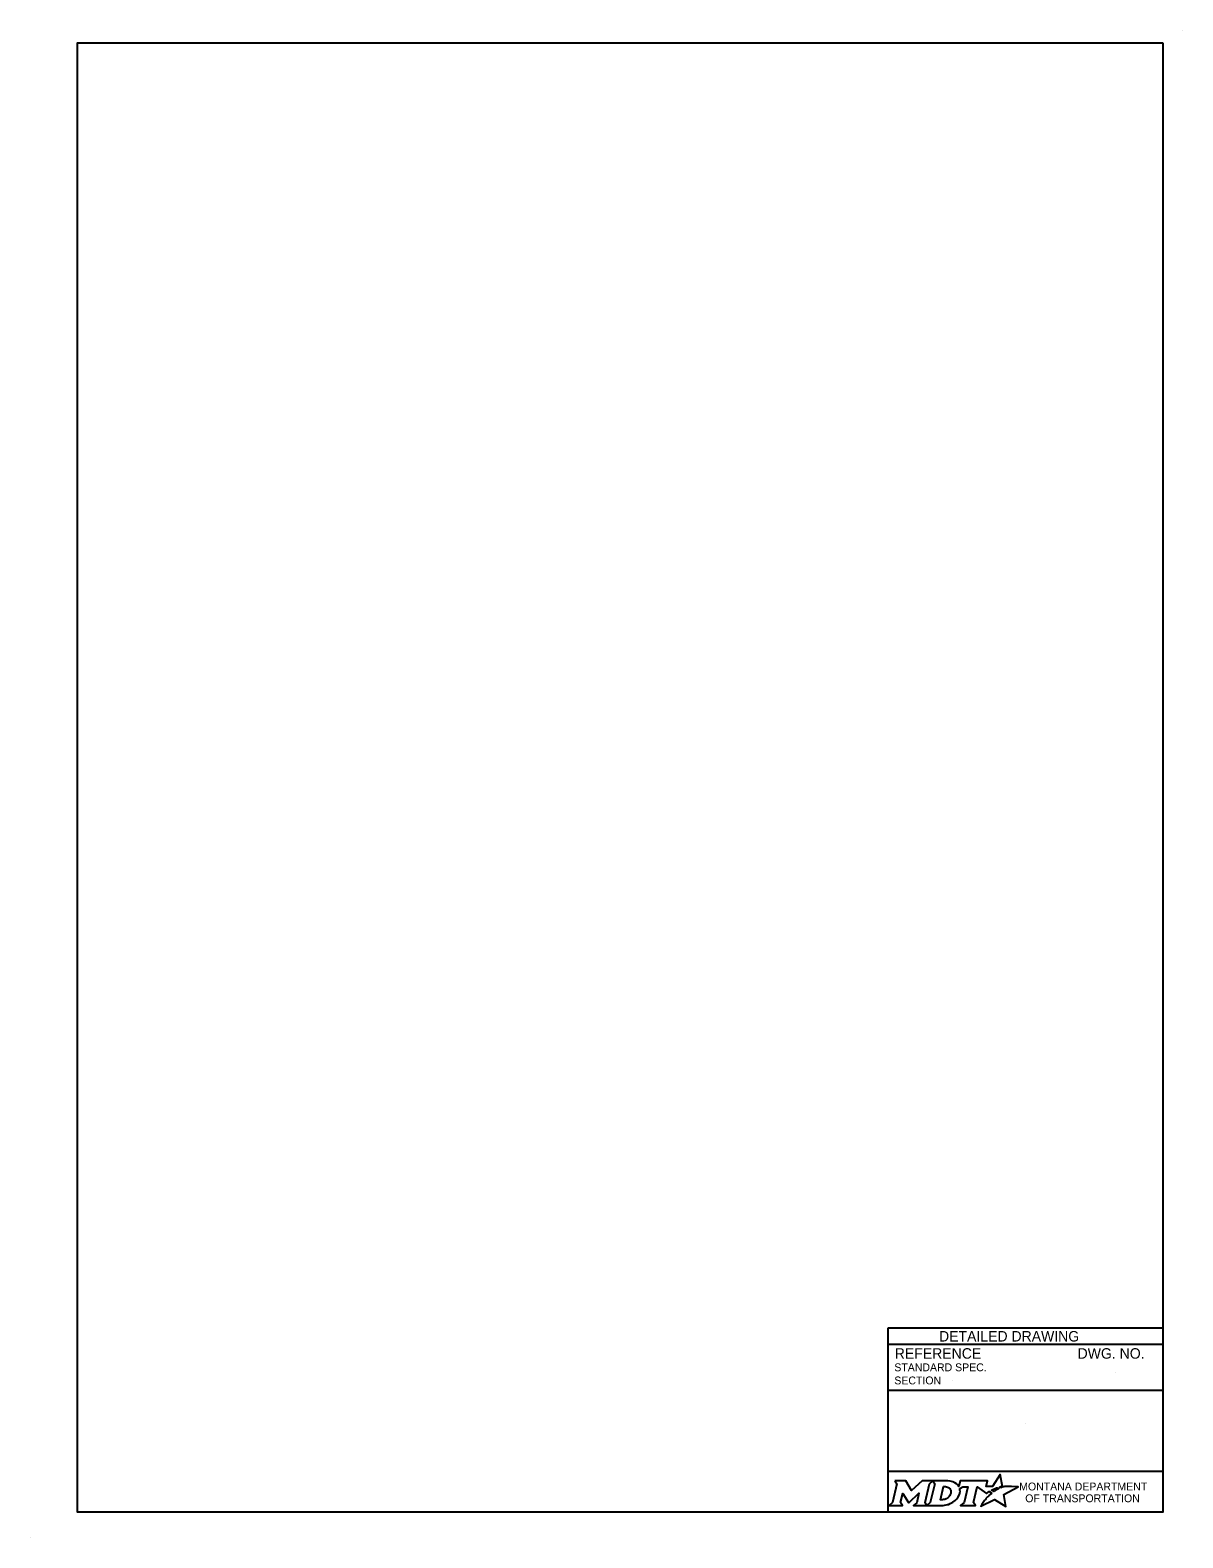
# Model space of a CAD drawing. Extents: x 49991 to 79985, y 47703 to 60542.
# Drawn here: x 49999.98 to 50008.76, y 49999.86 to 50011.36 of the extents above; entities that cross this region are included whole.
import ezdxf

# ---------------------------------------------------------------- set-up
doc = ezdxf.new("R2010")
doc.units = 0
doc.layers.add('Level 1', color=7, linetype='Continuous')
doc.layers.add('Level 2', color=7, linetype='Continuous')

msp = doc.modelspace()

# ---------------------------------------------------------------- linework, layer by layer
at = {"layer": 'Level 1'}
for p, q in [((50008.765, 50011.363), (50008.765, 50011.363)), ((49999.977, 49999.862), (49999.977, 49999.862))]:
    msp.add_line(p, q, dxfattribs=at)
msp.add_lwpolyline([(50008.615, 50011.263), (50000.336, 50011.263), (50000.336, 50000.062), (50008.615, 50000.062)], close=True, dxfattribs=at)
at = {"layer": 'Level 2'}
for p, q in [((50008.615, 50001.462), (50006.515, 50001.462)), ((50006.515, 50001.462), (50006.515, 50000.062)), ((50008.615, 50001.337), (50006.515, 50001.337)), ((50008.251, 50001.122), (50008.251, 50001.122)), ((50008.615, 50000.987), (50006.515, 50000.987)), ((50007.009, 50001.063), (50007.009, 50001.063)), ((50007.565, 50000.738), (50007.565, 50000.738)), ((50008.615, 50000.369), (50006.515, 50000.369))]:
    msp.add_line(p, q, dxfattribs=at)
for points in [[(50006.57, 50000.297), (50006.584, 50000.274), (50006.551, 50000.131), (50006.525, 50000.108), (50006.627, 50000.108), (50006.613, 50000.131), (50006.629, 50000.201), (50006.673, 50000.132), (50006.678, 50000.132), (50006.753, 50000.202), (50006.737, 50000.13), (50006.712, 50000.108), (50006.814, 50000.108), (50006.8, 50000.132), (50006.833, 50000.274)], [(50006.833, 50000.274), (50006.859, 50000.297), (50006.776, 50000.297), (50006.697, 50000.224), (50006.652, 50000.297), (50006.57, 50000.297)], [(50006.972, 50000.297), (50006.859, 50000.297), (50006.873, 50000.275), (50006.839, 50000.131), (50006.814, 50000.108), (50006.925, 50000.108)], [(50007.377, 50000.245), (50007.367, 50000.25), (50007.378, 50000.253), (50007.39, 50000.255), (50007.373, 50000.345), (50007.313, 50000.254), (50007.266, 50000.253), (50007.276, 50000.297), (50007.067, 50000.297), (50007.057, 50000.255), (50007.051, 50000.263)], [(50006.996, 50000.211), (50006.995, 50000.203), (50006.992, 50000.193), (50006.988, 50000.185), (50006.982, 50000.178), (50006.976, 50000.171), (50006.968, 50000.164), (50006.959, 50000.16), (50006.95, 50000.156), (50006.941, 50000.154), (50006.932, 50000.153), (50006.916, 50000.153), (50006.94, 50000.253), (50006.956, 50000.253), (50006.963, 50000.252), (50006.971, 50000.25), (50006.977, 50000.247), (50006.983, 50000.243), (50006.988, 50000.238), (50006.992, 50000.232), (50006.995, 50000.226), (50006.996, 50000.218), (50006.996, 50000.215), (50006.996, 50000.211)], [(50007.064, 50000.238), (50007.088, 50000.251), (50007.125, 50000.251), (50007.097, 50000.131), (50007.069, 50000.108), (50007.185, 50000.108), (50007.168, 50000.131), (50007.196, 50000.251), (50007.268, 50000.2), (50007.289, 50000.215), (50007.309, 50000.204)], [(50007.253, 50000.148), (50007.237, 50000.124), (50007.233, 50000.116), (50007.227, 50000.107), (50007.225, 50000.103), (50007.33, 50000.156), (50007.414, 50000.101), (50007.401, 50000.194), (50007.508, 50000.252), (50007.458, 50000.253), (50007.428, 50000.253), (50007.407, 50000.254), (50007.401, 50000.252), (50007.396, 50000.251), (50007.387, 50000.249), (50007.377, 50000.245)], [(50007.327, 50000.217), (50007.324, 50000.215), (50007.306, 50000.225), (50007.316, 50000.231), (50007.32, 50000.233), (50007.329, 50000.237), (50007.335, 50000.239), (50007.343, 50000.243), (50007.35, 50000.245), (50007.362, 50000.238), (50007.358, 50000.236), (50007.353, 50000.233), (50007.349, 50000.231), (50007.344, 50000.228), (50007.342, 50000.227), (50007.339, 50000.225), (50007.337, 50000.224), (50007.334, 50000.222), (50007.332, 50000.221), (50007.329, 50000.219), (50007.327, 50000.217)], [(50006.97, 50000.116), (50006.979, 50000.118), (50006.992, 50000.124), (50007.012, 50000.135)], [(50007.267, 50000.164), (50007.267, 50000.164)]]:
    msp.add_lwpolyline(points, dxfattribs=at)
for centre, radius, start, end in [((50006.951, 50000.236), 0.118, 300.9103, 339.1383), ((50006.995, 50000.219), 0.0709, 339.5329, 15.8582)]:
    msp.add_arc(centre, radius, start, end, dxfattribs=at)
for centre, major_axis, ratio, start_param, end_param in [((50006.97, 50000.25), (0.0834, -0.0037), 0.568097, 0.61298, 1.570796), ((50007.026, 50000.257), (0.0361, -0.0295), 0.469099, 1.225588, 1.570796), ((50007.276, 50000.174), (-0.0098, -0.0102), 0.016458, 3.141593, 6.279097), ((50007.297, 50000.194), (-0.0112, -0.0097), 0.021651, 3.157348, 6.283185), ((50006.925, 50000.257), (0, 0.148), 0.987302, 3.139398, 3.456847), ((50007.26, 50000.156), (-0.00694, -0.00806), 0.008222, 0, 3.137361)]:
    msp.add_ellipse(centre, major_axis=major_axis, ratio=ratio, start_param=start_param, end_param=end_param, dxfattribs=at)

# ---------------------------------------------------------------- texts
for s, height, p in [('DETAILED DRAWING', 0.0799, (50006.906, 50001.36)), ('REFERENCE', 0.08, (50006.568, 50001.229)), ('DWG. NO.', 0.08, (50007.962, 50001.229)), ('STANDARD SPEC.', 0.06, (50006.565, 50001.133)), ('SECTION', 0.06, (50006.565, 50001.033))]:
    msp.add_text(s, height=height, dxfattribs=at).set_placement(p)
for s, p in [('MONTANA DEPARTMENT', (50007.517, 50000.224)), ('OF TRANSPORTATION', (50007.563, 50000.134))]:
    msp.add_text(s, height=0.06, rotation=360, dxfattribs=at).set_placement(p)

doc.saveas('drawing.dxf')
